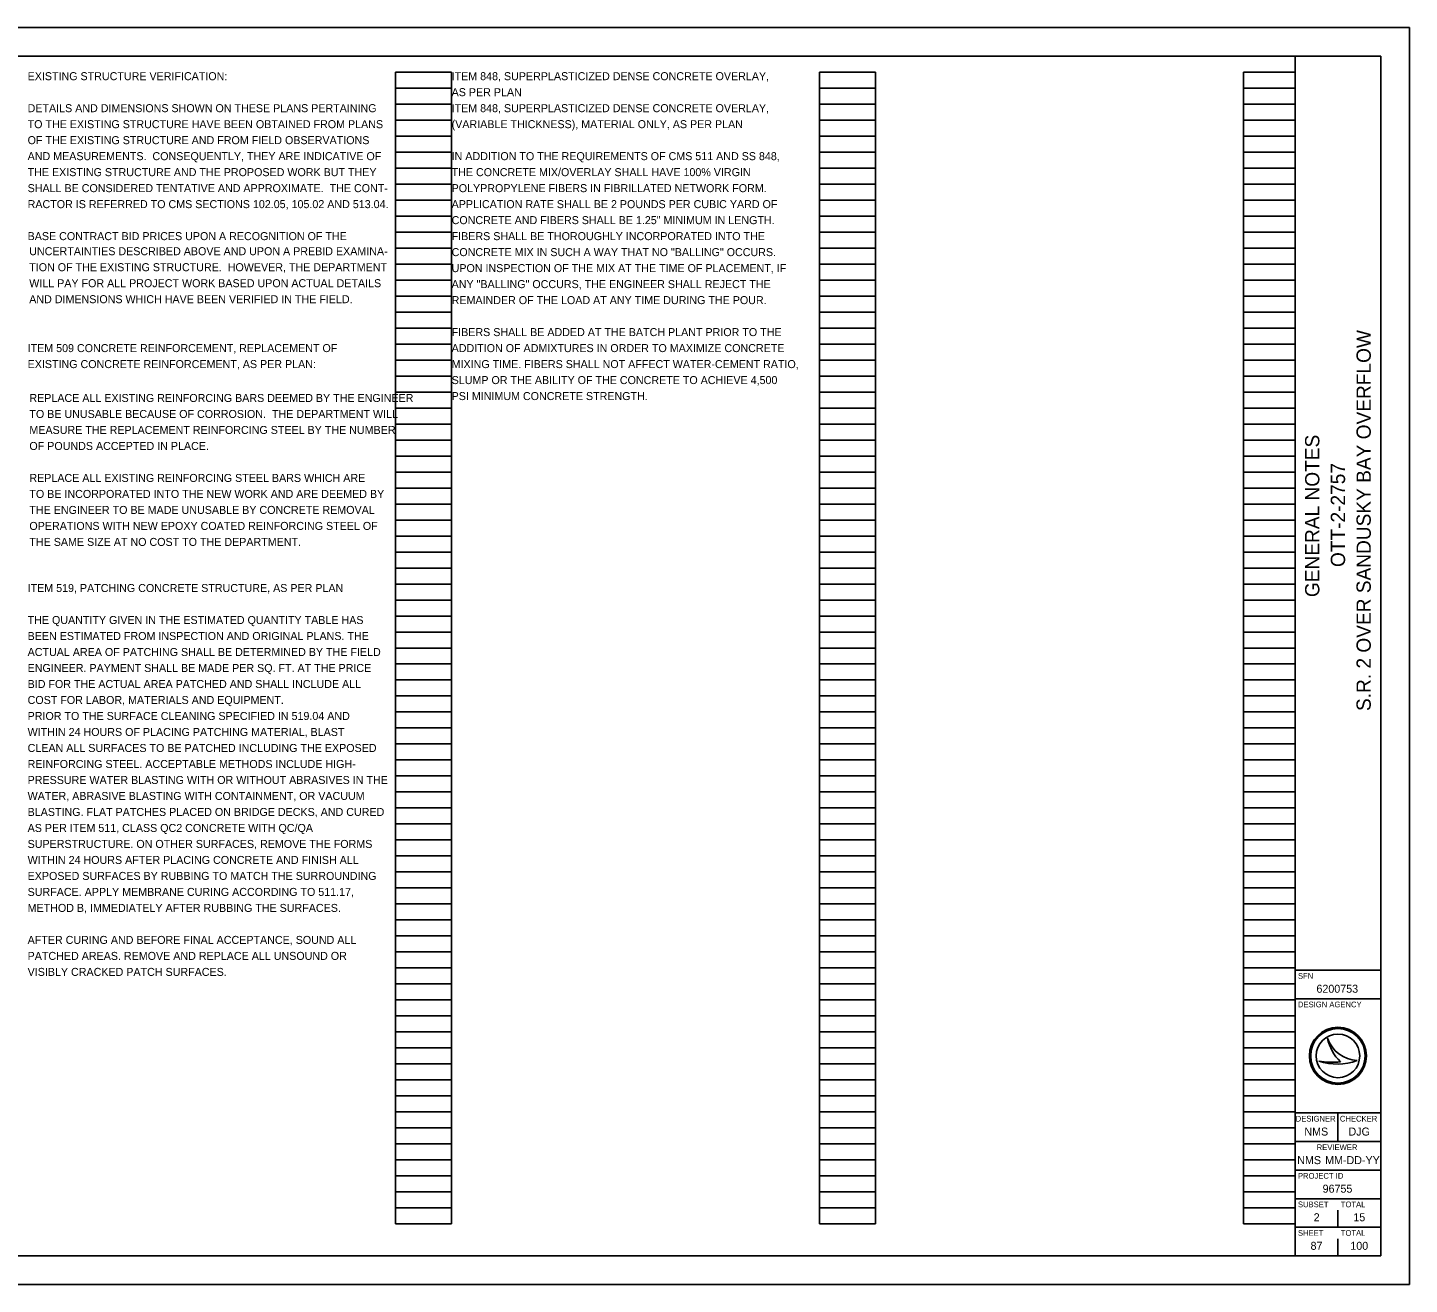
# Model space of a CAD drawing. Extents: x -11.1 to 34, y 0 to 22.
# Drawn here: x 9.82 to 34, y 0 to 22 of the extents above; entities that cross this region are included whole.
import ezdxf

# ---------------------------------------------------------------- set-up
doc = ezdxf.new("R2010")
doc.units = 0
for name, color, linetype in [('SH_Border', 7, 'Continuous'), ('SH_Cut_Line', 7, 'Continuous'), ('SH_Data', 7, 'Continuous'), ('SH_Text', 7, 'Continuous')]:
    doc.layers.add(name, color=color, linetype=linetype)

msp = doc.modelspace()

# ---------------------------------------------------------------- linework, layer by layer
at = {"layer": 'SH_Border'}
for p, q in [((32, 0.5), (32, 21.5)), ((32, 5.5), (33.5, 5.5)), ((32, 5), (33.5, 5)), ((32, 3), (33.5, 3)), ((32.75, 3), (32.75, 2.5)), ((32, 2.5), (33.5, 2.5)), ((32, 2), (33.5, 2)), ((32, 1.5), (33.5, 1.5)), ((32, 1), (33.5, 1))]:
    msp.add_line(p, q, dxfattribs=at)
msp.add_lwpolyline([(1.5, 21.5), (33.5, 21.5), (33.5, 0.5), (1.5, 0.5)], close=True, dxfattribs=at)
at = {"layer": 'SH_Cut_Line'}
msp.add_lwpolyline([(0, 0), (34, 0), (34, 22), (0, 22)], close=True, dxfattribs=at)
at = {"layer": 'SH_Data'}
for p, q in [((16.26, 1.06), (16.26, 21.22)), ((16.26, 21.22), (17.24, 21.22)), ((17.24, 1.06), (17.24, 21.22)), ((23.68, 1.06), (23.68, 21.22)), ((23.68, 21.22), (24.66, 21.22)), ((24.66, 1.06), (24.66, 21.22)), ((31.1, 1.06), (31.1, 21.22)), ((31.1, 21.22), (32, 21.22)), ((32, 1.06), (32, 21.22)), ((16.26, 20.94), (17.24, 20.94)), ((23.68, 20.94), (24.66, 20.94)), ((31.1, 20.94), (32, 20.94)), ((16.26, 20.66), (17.24, 20.66)), ((23.68, 20.66), (24.66, 20.66)), ((31.1, 20.66), (32, 20.66)), ((16.26, 20.38), (17.24, 20.38)), ((23.68, 20.38), (24.66, 20.38)), ((31.1, 20.38), (32, 20.38)), ((16.26, 20.1), (17.24, 20.1)), ((23.68, 20.1), (24.66, 20.1)), ((31.1, 20.1), (32, 20.1)), ((16.26, 19.82), (17.24, 19.82)), ((23.68, 19.82), (24.66, 19.82)), ((31.1, 19.82), (32, 19.82)), ((16.26, 19.54), (17.24, 19.54)), ((23.68, 19.54), (24.66, 19.54)), ((31.1, 19.54), (32, 19.54)), ((16.26, 19.26), (17.24, 19.26)), ((23.68, 19.26), (24.66, 19.26)), ((31.1, 19.26), (32, 19.26)), ((16.26, 18.98), (17.24, 18.98)), ((23.68, 18.98), (24.66, 18.98)), ((31.1, 18.98), (32, 18.98)), ((16.26, 18.7), (17.24, 18.7)), ((23.68, 18.7), (24.66, 18.7)), ((31.1, 18.7), (32, 18.7)), ((16.26, 18.42), (17.24, 18.42)), ((23.68, 18.42), (24.66, 18.42)), ((31.1, 18.42), (32, 18.42)), ((16.26, 18.14), (17.24, 18.14)), ((23.68, 18.14), (24.66, 18.14)), ((31.1, 18.14), (32, 18.14)), ((16.26, 17.86), (17.24, 17.86)), ((23.68, 17.86), (24.66, 17.86)), ((31.1, 17.86), (32, 17.86)), ((16.26, 17.58), (17.24, 17.58)), ((23.68, 17.58), (24.66, 17.58)), ((31.1, 17.58), (32, 17.58)), ((16.26, 17.3), (17.24, 17.3)), ((23.68, 17.3), (24.66, 17.3)), ((31.1, 17.3), (32, 17.3)), ((16.26, 17.02), (17.24, 17.02)), ((23.68, 17.02), (24.66, 17.02)), ((31.1, 17.02), (32, 17.02)), ((16.26, 16.74), (17.24, 16.74)), ((23.68, 16.74), (24.66, 16.74)), ((31.1, 16.74), (32, 16.74)), ((16.26, 16.46), (17.24, 16.46)), ((23.68, 16.46), (24.66, 16.46)), ((31.1, 16.46), (32, 16.46)), ((16.26, 16.18), (17.24, 16.18)), ((23.68, 16.18), (24.66, 16.18)), ((31.1, 16.18), (32, 16.18)), ((16.26, 15.9), (17.24, 15.9)), ((23.68, 15.9), (24.66, 15.9)), ((31.1, 15.9), (32, 15.9)), ((16.26, 15.62), (17.24, 15.62)), ((23.68, 15.62), (24.66, 15.62)), ((31.1, 15.62), (32, 15.62)), ((16.26, 15.34), (17.24, 15.34)), ((23.68, 15.34), (24.66, 15.34)), ((31.1, 15.34), (32, 15.34)), ((16.26, 15.06), (17.24, 15.06)), ((23.68, 15.06), (24.66, 15.06)), ((31.1, 15.06), (32, 15.06)), ((16.26, 14.78), (17.24, 14.78)), ((23.68, 14.78), (24.66, 14.78)), ((31.1, 14.78), (32, 14.78)), ((16.26, 14.5), (17.24, 14.5)), ((23.68, 14.5), (24.66, 14.5)), ((31.1, 14.5), (32, 14.5)), ((16.26, 14.22), (17.24, 14.22)), ((23.68, 14.22), (24.66, 14.22)), ((31.1, 14.22), (32, 14.22)), ((16.26, 13.94), (17.24, 13.94)), ((23.68, 13.94), (24.66, 13.94)), ((31.1, 13.94), (32, 13.94)), ((16.26, 13.66), (17.24, 13.66)), ((23.68, 13.66), (24.66, 13.66)), ((31.1, 13.66), (32, 13.66)), ((16.26, 13.38), (17.24, 13.38)), ((23.68, 13.38), (24.66, 13.38)), ((31.1, 13.38), (32, 13.38)), ((16.26, 13.1), (17.24, 13.1)), ((23.68, 13.1), (24.66, 13.1)), ((31.1, 13.1), (32, 13.1)), ((16.26, 12.82), (17.24, 12.82)), ((23.68, 12.82), (24.66, 12.82)), ((31.1, 12.82), (32, 12.82)), ((16.26, 12.54), (17.24, 12.54)), ((23.68, 12.54), (24.66, 12.54)), ((31.1, 12.54), (32, 12.54)), ((16.26, 12.26), (17.24, 12.26)), ((23.68, 12.26), (24.66, 12.26)), ((31.1, 12.26), (32, 12.26)), ((16.26, 11.98), (17.24, 11.98)), ((23.68, 11.98), (24.66, 11.98)), ((31.1, 11.98), (32, 11.98)), ((16.26, 11.7), (17.24, 11.7)), ((23.68, 11.7), (24.66, 11.7)), ((31.1, 11.7), (32, 11.7)), ((16.26, 11.42), (17.24, 11.42)), ((23.68, 11.42), (24.66, 11.42)), ((31.1, 11.42), (32, 11.42)), ((16.26, 11.14), (17.24, 11.14)), ((23.68, 11.14), (24.66, 11.14)), ((31.1, 11.14), (32, 11.14)), ((16.26, 10.86), (17.24, 10.86)), ((23.68, 10.86), (24.66, 10.86)), ((31.1, 10.86), (32, 10.86)), ((16.26, 10.58), (17.24, 10.58)), ((23.68, 10.58), (24.66, 10.58)), ((31.1, 10.58), (32, 10.58)), ((16.26, 10.3), (17.24, 10.3)), ((23.68, 10.3), (24.66, 10.3)), ((31.1, 10.3), (32, 10.3)), ((16.26, 10.02), (17.24, 10.02)), ((23.68, 10.02), (24.66, 10.02)), ((31.1, 10.02), (32, 10.02)), ((16.26, 9.74), (17.24, 9.74)), ((23.68, 9.74), (24.66, 9.74)), ((31.1, 9.74), (32, 9.74)), ((16.26, 9.46), (17.24, 9.46)), ((23.68, 9.46), (24.66, 9.46)), ((31.1, 9.46), (32, 9.46)), ((16.26, 9.18), (17.24, 9.18)), ((23.68, 9.18), (24.66, 9.18)), ((31.1, 9.18), (32, 9.18)), ((16.26, 8.9), (17.24, 8.9)), ((23.68, 8.9), (24.66, 8.9)), ((31.1, 8.9), (32, 8.9)), ((16.26, 8.62), (17.24, 8.62)), ((23.68, 8.62), (24.66, 8.62)), ((31.1, 8.62), (32, 8.62)), ((16.26, 8.34), (17.24, 8.34)), ((23.68, 8.34), (24.66, 8.34)), ((31.1, 8.34), (32, 8.34)), ((16.26, 8.06), (17.24, 8.06)), ((23.68, 8.06), (24.66, 8.06)), ((31.1, 8.06), (32, 8.06)), ((16.26, 7.78), (17.24, 7.78)), ((23.68, 7.78), (24.66, 7.78)), ((31.1, 7.78), (32, 7.78)), ((16.26, 7.5), (17.24, 7.5)), ((23.68, 7.5), (24.66, 7.5)), ((31.1, 7.5), (32, 7.5)), ((16.26, 7.22), (17.24, 7.22)), ((23.68, 7.22), (24.66, 7.22)), ((31.1, 7.22), (32, 7.22)), ((16.26, 6.94), (17.24, 6.94)), ((23.68, 6.94), (24.66, 6.94)), ((31.1, 6.94), (32, 6.94)), ((16.26, 6.66), (17.24, 6.66)), ((23.68, 6.66), (24.66, 6.66)), ((31.1, 6.66), (32, 6.66)), ((16.26, 6.38), (17.24, 6.38)), ((23.68, 6.38), (24.66, 6.38)), ((31.1, 6.38), (32, 6.38)), ((16.26, 6.1), (17.24, 6.1)), ((23.68, 6.1), (24.66, 6.1)), ((31.1, 6.1), (32, 6.1)), ((16.26, 5.82), (17.24, 5.82)), ((23.68, 5.82), (24.66, 5.82)), ((31.1, 5.82), (32, 5.82)), ((16.26, 5.54), (17.24, 5.54)), ((23.68, 5.54), (24.66, 5.54)), ((31.1, 5.54), (32, 5.54)), ((16.26, 5.26), (17.24, 5.26)), ((23.68, 5.26), (24.66, 5.26)), ((31.1, 5.26), (32, 5.26)), ((16.26, 4.98), (17.24, 4.98)), ((23.68, 4.98), (24.66, 4.98)), ((31.1, 4.98), (32, 4.98)), ((16.26, 4.7), (17.24, 4.7)), ((23.68, 4.7), (24.66, 4.7)), ((31.1, 4.7), (32, 4.7)), ((16.26, 4.42), (17.24, 4.42)), ((23.68, 4.42), (24.66, 4.42)), ((31.1, 4.42), (32, 4.42)), ((16.26, 4.14), (17.24, 4.14)), ((23.68, 4.14), (24.66, 4.14)), ((31.1, 4.14), (32, 4.14)), ((32.567, 4.31), (32.567, 4.31)), ((32.417, 3.91), (32.417, 3.91)), ((32.75, 4), (32.75, 4)), ((33.087, 3.919), (33.087, 3.919)), ((16.26, 3.86), (17.24, 3.86)), ((23.68, 3.86), (24.66, 3.86)), ((31.1, 3.86), (32, 3.86)), ((16.26, 3.58), (17.24, 3.58)), ((23.68, 3.58), (24.66, 3.58)), ((31.1, 3.58), (32, 3.58)), ((16.26, 3.3), (17.24, 3.3)), ((23.68, 3.3), (24.66, 3.3)), ((31.1, 3.3), (32, 3.3)), ((16.26, 3.02), (17.24, 3.02)), ((23.68, 3.02), (24.66, 3.02)), ((31.1, 3.02), (32, 3.02)), ((16.26, 2.74), (17.24, 2.74)), ((23.68, 2.74), (24.66, 2.74)), ((31.1, 2.74), (32, 2.74)), ((16.26, 2.46), (17.24, 2.46)), ((23.68, 2.46), (24.66, 2.46)), ((31.1, 2.46), (32, 2.46)), ((16.26, 2.18), (17.24, 2.18)), ((23.68, 2.18), (24.66, 2.18)), ((31.1, 2.18), (32, 2.18)), ((16.26, 1.9), (17.24, 1.9)), ((23.68, 1.9), (24.66, 1.9)), ((31.1, 1.9), (32, 1.9)), ((16.26, 1.62), (17.24, 1.62)), ((23.68, 1.62), (24.66, 1.62)), ((31.1, 1.62), (32, 1.62)), ((16.26, 1.34), (17.24, 1.34)), ((23.68, 1.34), (24.66, 1.34)), ((31.1, 1.34), (32, 1.34)), ((32.75, 1), (32.75, 1.3)), ((16.26, 1.06), (17.24, 1.06)), ((23.68, 1.06), (24.66, 1.06)), ((31.1, 1.06), (32, 1.06)), ((32.75, 0.5), (32.75, 0.8)), ((32.375, 0.675), (32.375, 0.675))]:
    msp.add_line(p, q, dxfattribs=at)
for radius in [0.5, 0.477, 0.477, 0.382]:
    msp.add_circle((32.75, 4), radius, dxfattribs=at)
for centre, radius, start, end in [((33.116, 4.498), 0.58, 198.9257, 198.9319), ((33.347, 4.47), 0.796, 191.6379, 191.6421), ((33.116, 4.498), 0.58, 198.9319, 267.1657), ((33.347, 4.47), 0.796, 191.6421, 226.0947), ((32.739, 4.87), 1.013, 251.4576, 290.0832), ((32.648, 5.154), 1.266, 259.4964, 259.4995), ((32.739, 4.87), 1.013, 251.4527, 251.4576), ((32.648, 5.154), 1.266, 259.4995, 276.6672)]:
    msp.add_arc(centre, radius, start, end, dxfattribs=at)

# ---------------------------------------------------------------- texts
for s, p in [('S.R. 2 OVER SANDUSKY BAY OVERFLOW', (33.325, 10.037)), ('GENERAL NOTES', (32.425, 12.031)), ('OTT-2-2757', (32.875, 12.557))]:
    msp.add_text(s, height=0.25, rotation=90, dxfattribs=at).set_placement(p)
for s, height, p in [('SFN', 0.1, (32.05, 5.35)), ('6200753', 0.14, (32.374, 5.105)), ('DESIGN AGENCY', 0.1, (32.05, 4.85)), ('DESIGNER', 0.1, (32.011, 2.85)), ('CHECKER', 0.1, (32.784, 2.85)), ('NMS', 0.14, (32.163, 2.605)), ('DJG', 0.14, (32.935, 2.605)), ('REVIEWER', 0.1, (32.378, 2.35)), ('NMS', 0.14, (32.038, 2.105)), ('MM-DD-YY', 0.14, (32.526, 2.105)), ('PROJECT ID', 0.1, (32.05, 1.85)), ('96755', 0.14, (32.482, 1.605)), ('SUBSET', 0.1, (32.05, 1.35)), ('TOTAL', 0.1, (32.8, 1.35)), ('2', 0.14, (32.326, 1.105)), ('15', 0.14, (33.02, 1.105)), ('SHEET', 0.1, (32.05, 0.85)), ('87', 0.14, (32.271, 0.605)), ('TOTAL', 0.1, (32.8, 0.85)), ('100', 0.14, (32.967, 0.605))]:
    msp.add_text(s, height=height, dxfattribs=at).set_placement(p)
at = {"layer": 'SH_Text'}
for s, p in [('EXISTING STRUCTURE VERIFICATION:', (9.82, 21.08)), ('ITEM 848, SUPERPLASTICIZED DENSE CONCRETE OVERLAY,', (17.24, 21.08)), ('AS PER PLAN', (17.24, 20.8)), ('DETAILS AND DIMENSIONS SHOWN ON THESE PLANS PERTAINING', (9.82, 20.52)), ('ITEM 848, SUPERPLASTICIZED DENSE CONCRETE OVERLAY, ', (17.24, 20.52)), ('TO THE EXISTING STRUCTURE HAVE BEEN OBTAINED FROM PLANS', (9.82, 20.24)), ('(VARIABLE THICKNESS), MATERIAL ONLY, AS PER PLAN', (17.24, 20.24)), ('OF THE EXISTING STRUCTURE AND FROM FIELD OBSERVATIONS', (9.82, 19.96)), ('AND MEASUREMENTS.  CONSEQUENTLY, THEY ARE INDICATIVE OF', (9.82, 19.68)), ('IN ADDITION TO THE REQUIREMENTS OF CMS 511 AND SS 848, ', (17.24, 19.68)), ('THE EXISTING STRUCTURE AND THE PROPOSED WORK BUT THEY', (9.82, 19.4)), ('THE CONCRETE MIX/OVERLAY SHALL HAVE 100% VIRGIN ', (17.24, 19.4)), ('SHALL BE CONSIDERED TENTATIVE AND APPROXIMATE.  THE CONT-', (9.82, 19.12)), ('POLYPROPYLENE FIBERS IN FIBRILLATED NETWORK FORM. ', (17.24, 19.12)), ('RACTOR IS REFERRED TO CMS SECTIONS 102.05, 105.02 AND 513.04.', (9.82, 18.84)), ('APPLICATION RATE SHALL BE 2 POUNDS PER CUBIC YARD OF ', (17.24, 18.84)), ('CONCRETE AND FIBERS SHALL BE 1.25" MINIMUM IN LENGTH. ', (17.24, 18.56)), ('BASE CONTRACT BID PRICES UPON A RECOGNITION OF THE', (9.82, 18.28)), ('FIBERS SHALL BE THOROUGHLY INCORPORATED INTO THE ', (17.24, 18.28)), ('UNCERTAINTIES DESCRIBED ABOVE AND UPON A PREBID EXAMINA-', (9.848, 18.016)), ('CONCRETE MIX IN SUCH A WAY THAT NO "BALLING" OCCURS. ', (17.24, 18)), ('TION OF THE EXISTING STRUCTURE.  HOWEVER, THE DEPARTMENT', (9.848, 17.736)), ('UPON INSPECTION OF THE MIX AT THE TIME OF PLACEMENT, IF ', (17.24, 17.72)), ('WILL PAY FOR ALL PROJECT WORK BASED UPON ACTUAL DETAILS', (9.848, 17.456)), ('ANY "BALLING" OCCURS, THE ENGINEER SHALL REJECT THE ', (17.24, 17.44)), ('AND DIMENSIONS WHICH HAVE BEEN VERIFIED IN THE FIELD.', (9.848, 17.176)), ('REMAINDER OF THE LOAD AT ANY TIME DURING THE POUR.', (17.24, 17.16)), ('FIBERS SHALL BE ADDED AT THE BATCH PLANT PRIOR TO THE ', (17.24, 16.6)), ('ITEM 509 CONCRETE REINFORCEMENT, REPLACEMENT OF ', (9.82, 16.32)), ('ADDITION OF ADMIXTURES IN ORDER TO MAXIMIZE CONCRETE ', (17.24, 16.32)), ('EXISTING CONCRETE REINFORCEMENT, AS PER PLAN: ', (9.82, 16.04)), ('MIXING TIME. FIBERS SHALL NOT AFFECT WATER-CEMENT RATIO, ', (17.24, 16.04)), ('SLUMP OR THE ABILITY OF THE CONCRETE TO ACHIEVE 4,500 ', (17.24, 15.76)), ('REPLACE ALL EXISTING REINFORCING BARS DEEMED BY THE ENGINEER', (9.851, 15.447)), ('PSI MINIMUM CONCRETE STRENGTH.', (17.24, 15.48)), ('TO BE UNUSABLE BECAUSE OF CORROSION.  THE DEPARTMENT WILL', (9.851, 15.167)), ('MEASURE THE REPLACEMENT REINFORCING STEEL BY THE NUMBER', (9.851, 14.887)), ('OF POUNDS ACCEPTED IN PLACE.', (9.851, 14.607)), ('REPLACE ALL EXISTING REINFORCING STEEL BARS WHICH ARE', (9.851, 14.047)), ('TO BE INCORPORATED INTO THE NEW WORK AND ARE DEEMED BY', (9.851, 13.767)), ('THE ENGINEER TO BE MADE UNUSABLE BY CONCRETE REMOVAL', (9.851, 13.487)), ('OPERATIONS WITH NEW EPOXY COATED REINFORCING STEEL OF', (9.851, 13.207)), ('THE SAME SIZE AT NO COST TO THE DEPARTMENT.', (9.851, 12.927)), ('ITEM 519, PATCHING CONCRETE STRUCTURE, AS PER PLAN', (9.82, 12.12)), ('THE QUANTITY GIVEN IN THE ESTIMATED QUANTITY TABLE HAS', (9.82, 11.56)), ('BEEN ESTIMATED FROM INSPECTION AND ORIGINAL PLANS. THE', (9.82, 11.28)), ('ACTUAL AREA OF PATCHING SHALL BE DETERMINED BY THE FIELD', (9.82, 11)), ('ENGINEER. PAYMENT SHALL BE MADE PER SQ. FT. AT THE PRICE', (9.82, 10.72)), ('BID FOR THE ACTUAL AREA PATCHED AND SHALL INCLUDE ALL', (9.82, 10.44)), ('COST FOR LABOR, MATERIALS AND EQUIPMENT.', (9.82, 10.16)), ('PRIOR TO THE SURFACE CLEANING SPECIFIED IN 519.04 AND', (9.82, 9.88)), ('WITHIN 24 HOURS OF PLACING PATCHING MATERIAL, BLAST', (9.82, 9.6)), ('CLEAN ALL SURFACES TO BE PATCHED INCLUDING THE EXPOSED', (9.82, 9.32)), ('REINFORCING STEEL. ACCEPTABLE METHODS INCLUDE HIGH-', (9.82, 9.04)), ('PRESSURE WATER BLASTING WITH OR WITHOUT ABRASIVES IN THE', (9.82, 8.76)), ('WATER, ABRASIVE BLASTING WITH CONTAINMENT, OR VACUUM', (9.82, 8.48)), ('BLASTING. FLAT PATCHES PLACED ON BRIDGE DECKS, AND CURED', (9.82, 8.2)), ('AS PER ITEM 511, CLASS QC2 CONCRETE WITH QC/QA', (9.82, 7.92)), ('SUPERSTRUCTURE. ON OTHER SURFACES, REMOVE THE FORMS', (9.82, 7.64)), ('WITHIN 24 HOURS AFTER PLACING CONCRETE AND FINISH ALL', (9.82, 7.36)), ('EXPOSED SURFACES BY RUBBING TO MATCH THE SURROUNDING', (9.82, 7.08)), ('SURFACE. APPLY MEMBRANE CURING ACCORDING TO 511.17,', (9.82, 6.8)), ('METHOD B, IMMEDIATELY AFTER RUBBING THE SURFACES.', (9.82, 6.52)), ('AFTER CURING AND BEFORE FINAL ACCEPTANCE, SOUND ALL', (9.82, 5.96)), ('PATCHED AREAS. REMOVE AND REPLACE ALL UNSOUND OR', (9.82, 5.68)), ('VISIBLY CRACKED PATCH SURFACES.', (9.82, 5.4))]:
    msp.add_text(s, height=0.14, dxfattribs=at).set_placement(p)

doc.saveas('drawing.dxf')
